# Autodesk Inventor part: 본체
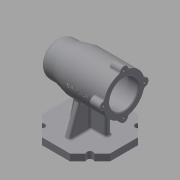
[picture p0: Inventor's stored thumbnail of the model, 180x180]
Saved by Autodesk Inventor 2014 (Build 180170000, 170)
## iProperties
Created: 2021-01
Part Number: 본체
Material: Generic
Document SubType Name: Modeling
Designer: kh
Density: 1 g/cm^3
Appearance: Default
Author: kh
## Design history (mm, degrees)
sketch "Sketch1" dims "d0" = 100
  geometry: L1 (50, 20.711)-(50, -20.711); L2 (20.711, -50)-(-20.711, -50); L3 (-50, -20.711)-(-50, 20.711); L4 (-20.711, 50)-(20.711, 50); L5 (35.355, 35.355)-(-35.355, -35.355); L6 (-35.355, 35.355)-(35.355, -35.355); L7 (-50, 0)-(50, 0); L8 (0, 50)-(0, -50); L9 (-50, 20.711)-(-38.537, 32.173); L10 (-32.173, 38.537)-(-20.711, 50); L11 (-20.711, -50)-(-32.173, -38.537); L12 (-38.537, -32.173)-(-50, -20.711); L13 (50, -20.711)-(38.537, -32.173); L14 (32.173, -38.537)-(20.711, -50); L15 (20.711, 50)-(32.173, 38.537); L16 (38.537, 32.173)-(50, 20.711); A1 r 4.5 centre (-35.355, -35.355) between (-32.173, -38.537) and (-38.537, -32.173); A2 r 4.5 centre (35.355, -35.355) between (38.537, -32.173) and (32.173, -38.537); A3 r 4.5 centre (-35.355, 35.355) between (-38.537, 32.173) and (-32.173, 38.537); A4 r 4.5 centre (35.355, 35.355) between (32.173, 38.537) and (38.537, 32.173); 4 further points
  constraints: 32 end point, 8 point on circle, 6 coincident, 6 midpoint, 4 centre point, 1 vertical alignment, 11 other
  dimensions: "d1" = 9 diameter of A1; "d2" = 9 diameter of A2; "d3" = 9 diameter of A3; "d4" = 9 diameter of A4; "d6" = 50 distance between parallel lines of L1 L8 (derived); "d7" = 45 deg angle of L6 L7
extrude "Extrusion1" new body sketch "Sketch1" distance "d8" = 10; taper "d9" = 0 deg
sketch "Sketch2"
  geometry: L1 (0, 0)-(0, 75); L2 (65.016, 75)-(-65.016, 75); L3 (-50, 75)-(-50, 105); L4 (-50, 105)-(10, 105); L5 (10, 105)-(30, 100); L6 (30, 100)-(50, 100); L7 (50, 100)-(50, 75); L8 (-50, 0)-(-50, 10) reference; L9 (-50, 96)-(-35, 96); L10 (-35, 96)-(-35, 99); L11 (-35, 99)-(7, 99); L12 (7, 99)-(7, 96); L13 (7, 96)-(19, 96); L14 (19, 96)-(19, 92.5); L15 (19, 92.5)-(37, 92.5); L16 (37, 92.5)-(37, 91); L17 (37, 91)-(41, 91); L18 (41, 91)-(41, 85.5); L19 (41, 85.5)-(44, 85.5); L20 (44, 85.5)-(44, 75)
  constraints: 38 end point, 9 parallel, 7 perpendicular, 4 point on line, 2 collinear, 1 midpoint, 1 vertical
  dimensions: "d10" = 75 distance of L1.end L1.start; "d11" = 60 diameter of L4 L2; "d12" = 50 diameter of L6 L2; "d13" = 100 distance between parallel lines of L7 L3; "d14" = 20 distance from line of L7 L5.end; "d15" = 40 distance from line of L7 L4.end; "d16" = 42 diameter of L9 L2; "d17" = 48 diameter of L11 L2; "d18" = 42 diameter of L13 L2; "d19" = 35 diameter of L15 L2; "d20" = 32 diameter of L17 L2; "d21" = 21 diameter of L19 L2; "d22" = 15 distance between parallel lines of L3 L10; "d28" = 42 distance between parallel lines of L12 L10; "d31" = 3 distance between parallel lines of L20 L18; "d32" = 12 distance between parallel lines of L12 L14; "d33" = 18 distance between parallel lines of L16 L14; "d34" = 4 distance between parallel lines of L16 L18
revolve "Revolution1" sketch "Sketch2" stored, may be unused: angle "d35" = 90 deg
sketch "Sketch3"
  geometry: L1 (32.173, 10)-(20.711, 10) reference; L2 (30.855, 10)-(38.537, 10) reference; L3 (50, 10)-(38.537, 10) reference; L4 (-50, 45)-(10, 45) reference; L5 (10, 45)-(30, 50) reference; L6 (27, 10)-(19.724, 47.431); L7 (50, 0)-(50, 10) reference; L8 (-27, 45)-(-27, 10); L9 (-50, 0)-(-50, 10) reference; 1 further point
  constraints: 4 end point, 3 point on line, 1 parallel
  dimensions: "d36" = 101 deg angle of L2 L6; "d37" = 23 distance from line of L7 L6.start; "d38" = 23 distance between parallel lines of L9 L8
feature "Rib1" dims "d39" = 1, "d40" = 8, "d41" = 0, "d42" = 0, "d43" = 1, "d44" = 1
feature "Rib2" dims "d45" = 1, "d46" = 8, "d47" = 0, "d48" = 0, "d49" = 1, "d50" = 1
sketch "Sketch4"
  geometry: L1 (30.855, 10)-(38.537, 10) reference; L2 (20.711, 10)-(32.173, 10) reference; L3 (-32.173, 10)-(-20.711, 10) reference; L4 (-38.537, 10)-(-30.855, 10) reference; L5 (-35, 10)-(-19.606, 52.293); L6 (35, 10)-(19.606, 52.293); L7 (-50, 0)-(-50, 10) reference; L8 (50, 0)-(50, 10) reference; A1 r 30 centre (0, 75) between (-19.606, 52.293) and (19.606, 52.293) reference; 1 further point
  constraints: 4 end point, 2 point on circle, 2 point on line
  dimensions: "d51" = 110 deg angle of L1 L6; "d52" = 110 deg angle of L4 L5; "d53" = 15 distance from line of L7 L5.start; "d54" = 15 distance from line of L6.start L8
feature "Rib3" dims "d55" = 1, "d56" = 8, "d57" = 0, "d58" = 0, "d59" = 1, "d60" = 1
feature "Rib4" dims "d61" = 1, "d62" = 8, "d63" = 0, "d64" = 0, "d65" = 1, "d66" = 1
sketch "Sketch5"
  geometry: L1 (-30, 0)-(30, 0); L2 (0, -30)-(0, 30); C1 r 6 at (-30, 0); C2 r 6 at (0, 30); C3 r 6 at (30, 0); C4 r 6 at (0, -30); A1 r 30 centre (0, 0) between (-30, 0) and (30, 0) reference; 3 further points
  constraints: 4 centre point, 4 coincident, 4 end point, 4 midpoint, 4 point on circle, 1 horizontal, 1 perpendicular
  dimensions: "d67" = 12 diameter of C1; "d68" = 12 diameter of C2; "d69" = 12 diameter of C3; "d70" = 12 diameter of C4
extrude "Extrusion2" join sketch "Sketch5" distance "d71" = 16; taper "d72" = 0 deg
sketch "Sketch6"
  geometry: A1 r 6 centre (0, 0) between (0.6, 5.97) and (0.6, -5.97) reference; A2 r 6 centre (30, -30) between (24.03, -29.4) and (35.97, -29.4) reference; A3 r 6 centre (60, 0) between (59.4, -5.97) and (59.4, 5.97) reference; A4 r 6 centre (30, 30) between (35.97, 29.4) and (24.03, 29.4) reference; 5 further points
  constraints: 4 coincident
hole "Hole1" sketch "Sketch6" at (0, 0), (30, -30), (60, 0), (30, 30) diameter "d73" = 3.242; stored, may be unused: countersink angle "d77" = 90 deg, drill point angle "d79" = 118 deg; dims "d74" = 8, "d75" = 4, "d76" = 2, "d78" = 10
workplane "Work Plane1"
sketch "Sketch7"
  geometry: L1 (-5.162, 79.27)-(29.162, 79.27); L2 (29.162, 79.27)-(29.162, 70.73); L3 (29.162, 70.73)-(-5.162, 70.73); L4 (-5.162, 70.73)-(-5.162, 79.27); L5 (-5.162, 79.27)-(29.162, 70.73); L6 (50, 96)-(50, 54) reference; L7 (-50, 100)-(-50, 50) reference; L8 (50, 75)-(-50, 75); 2 further points
  constraints: 4 end point, 3 midpoint, 1 point on line, 2 other
  dimensions: "d81" = 38 distance from line of L6 point (12, 75)
emboss "Emboss1" sketch "Sketch7" dims "d82" = 0.5, "d83" = 0
fillet "Fillet1" dims "d84" = 3
fillet "Fillet2" dims "d85" = 3
fillet "Fillet3" dims "d86" = 3
fillet "Fillet4" dims "d87" = 0.3
fillet "Fillet5" dims "d88" = 3
chamfer "Chamfer1" distance "d89" = 1; stored, may be unused: second distance "d90" = 2, angle "d91" = 45 deg
fillet "Fillet6" dims "d92" = 10
fillet "Fillet7" dims "d93" = 3
fillet "Fillet8" dims "d94" = 1
fillet "Fillet9" dims "d95" = 3
fillet "Fillet10" dims "d96" = 1
fillet "Fillet11" dims "d97" = 3
fillet "Fillet12" dims "d98" = 1
body "Solid1"
